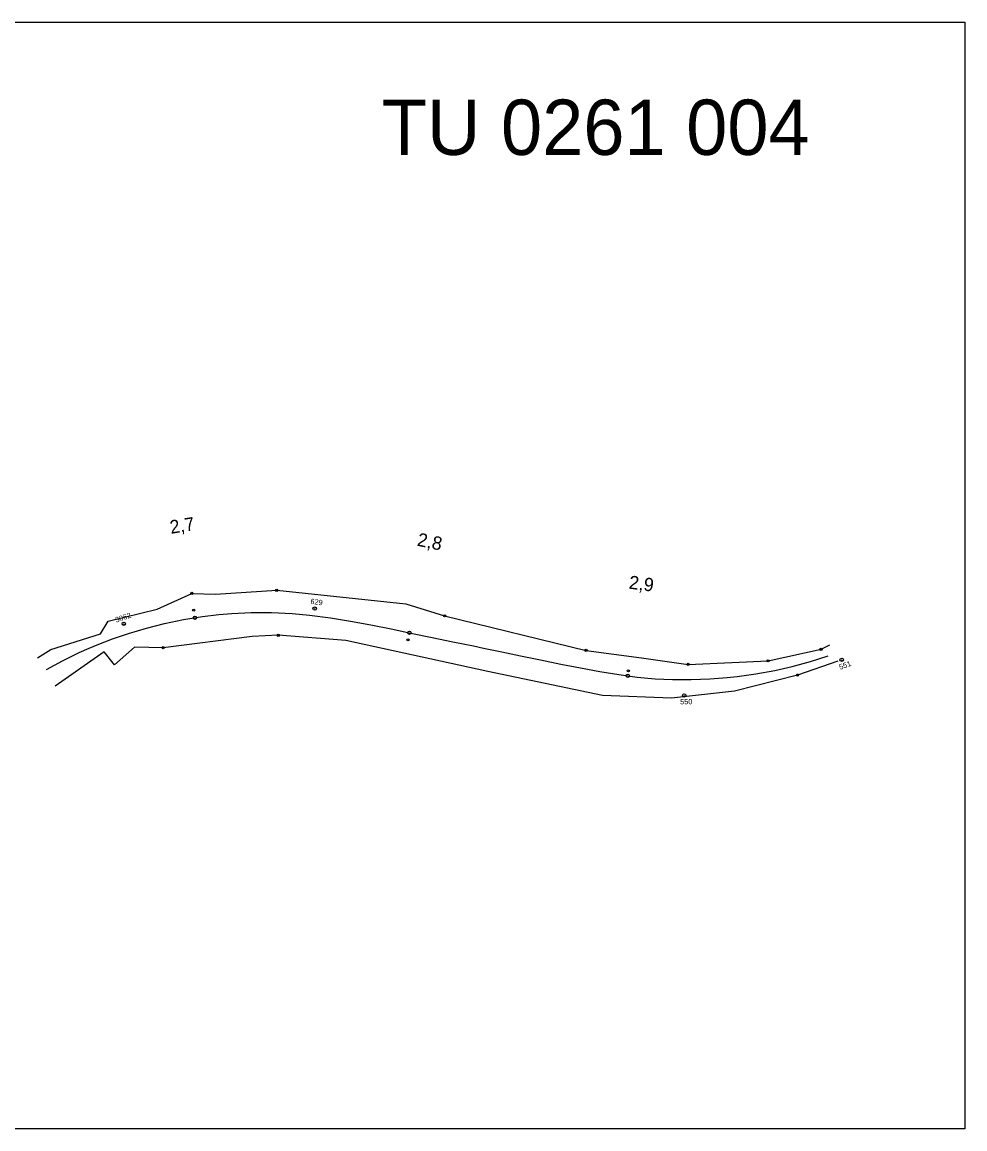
# Model space of a CAD drawing. Extents: x -849500 to -843400, y -1061500 to -1052696.
# Drawn here: x -843826 to -843400, y -1061500 to -1061000 of the extents above; entities that cross this region are included whole.
import ezdxf

# ---------------------------------------------------------------- set-up
doc = ezdxf.new("R2010")
doc.units = 0
for name, color, linetype in [('Level 1', 7, 'Continuous'), ('Level 2', 7, 'Continuous'), ('Vrstva 1', 7, 'Continuous'), ('Vrstva 53', 7, 'Continuous'), ('Vrstva 63', 7, 'Continuous'), ('Vrstva 7', 7, 'Continuous')]:
    doc.layers.add(name, color=color, linetype=linetype)

msp = doc.modelspace()

# ---------------------------------------------------------------- linework, layer by layer
at = {"layer": 'Level 1'}
msp.add_lwpolyline([(-844100, -1061500), (-844100, -1061000), (-843400, -1061000), (-843400, -1061500), (-844100, -1061500)], dxfattribs=at)
at = {"layer": 'Vrstva 1'}
msp.add_lwpolyline([(-843814.8, -1061292.46), (-843807.55, -1061288.51), (-843800.05, -1061284.84), (-843795.59, -1061282.83), (-843792.03, -1061281.34), (-843784.97, -1061278.61), (-843777.74, -1061276.13), (-843769.61, -1061273.72), (-843761.54, -1061271.7), (-843752.93, -1061269.93), (-843744.31, -1061268.56), (-843737, -1061267.68), (-843731.14, -1061267.17), (-843722.35, -1061266.75), (-843713.28, -1061266.75), (-843703.86, -1061267.17), (-843695.99, -1061267.88), (-843686.54, -1061269.1), (-843677.48, -1061270.59), (-843668.34, -1061272.3), (-843659.18, -1061274.15), (-843650.24, -1061275.99), (-843640.69, -1061277.96), (-843631.28, -1061279.9), (-843622.03, -1061281.82), (-843617.49, -1061282.77), (-843609.21, -1061284.48), (-843600.78, -1061286.23), (-843591.65, -1061288.12), (-843582.54, -1061289.99), (-843573.66, -1061291.77), (-843564.83, -1061293.4), (-843556.32, -1061294.8), (-843547.97, -1061295.88), (-843539.88, -1061296.61), (-843532.11, -1061296.98), (-843523.63, -1061297.04), (-843515.26, -1061296.73), (-843507.43, -1061296.12), (-843502.84, -1061295.63), (-843494.35, -1061294.43), (-843485.91, -1061292.87), (-843478.02, -1061291.08), (-843469.68, -1061288.8), (-843461.7, -1061286.27)], dxfattribs=at)
at = {"layer": 'Vrstva 53'}
for p, q in [((-843749.26, -1061258.08), (-843749.16, -1061258.08)), ((-843710.92, -1061256.67), (-843710.82, -1061256.67)), ((-843635.07, -1061268.21), (-843634.97, -1061268.21)), ((-843710.21, -1061277.01), (-843710.11, -1061277.01)), ((-843762.2, -1061282.64), (-843762.1, -1061282.64)), ((-843571.18, -1061283.83), (-843571.08, -1061283.83)), ((-843465, -1061283.35), (-843464.9, -1061283.35)), ((-843488.96, -1061288.55), (-843488.86, -1061288.55)), ((-843525.03, -1061290.18), (-843524.93, -1061290.18)), ((-843475.67, -1061295), (-843475.57, -1061295))]:
    msp.add_line(p, q, dxfattribs=at)
for points in [[(-843818.86, -1061287.16), (-843812.93, -1061283.41), (-843790.42, -1061276.31), (-843787, -1061270.65), (-843764.85, -1061265.22), (-843749.21, -1061258.08), (-843738.44, -1061258.37), (-843710.87, -1061256.67), (-843652.6, -1061262.75), (-843635.02, -1061268.21), (-843571.13, -1061283.83), (-843546.06, -1061287.23), (-843524.98, -1061290.18), (-843505.26, -1061289.35), (-843488.91, -1061288.55), (-843464.95, -1061283.35), (-843461.05, -1061281.3)], [(-843457.33, -1061288.75), (-843475.62, -1061295), (-843504.06, -1061302.23), (-843532.5, -1061305.38), (-843563.75, -1061304.23), (-843615.53, -1061293.42), (-843679.63, -1061279.35), (-843710.16, -1061277.01), (-843722.02, -1061277.52), (-843762.15, -1061282.64), (-843775.05, -1061282.39), (-843784.12, -1061290.32), (-843788.83, -1061284.48), (-843811.01, -1061300.02)]]:
    msp.add_lwpolyline(points, dxfattribs=at)
for centre in [(-843749.21, -1061258.08), (-843710.87, -1061256.67), (-843635.02, -1061268.21), (-843710.16, -1061277.01), (-843762.15, -1061282.64), (-843571.13, -1061283.83), (-843464.95, -1061283.35), (-843524.98, -1061290.18), (-843488.91, -1061288.55), (-843475.62, -1061295)]:
    msp.add_circle(centre, 0.499, dxfattribs=at)
at = {"layer": 'Vrstva 63'}
for p, q in [((-843693.76, -1061264.93), (-843693.66, -1061264.93)), ((-843780.01, -1061271.79), (-843779.91, -1061271.79)), ((-843455.7, -1061288.04), (-843455.6, -1061288.04)), ((-843526.79, -1061304.16), (-843526.69, -1061304.16))]:
    msp.add_line(p, q, dxfattribs=at)
for centre in [(-843693.71, -1061264.93), (-843779.96, -1061271.79), (-843455.65, -1061288.04), (-843526.74, -1061304.16)]:
    msp.add_circle(centre, 0.756, dxfattribs=at)
at = {"layer": 'Vrstva 7'}
for p, q in [((-843748.39, -1061265.69), (-843748.29, -1061265.68)), ((-843651.51, -1061279.09), (-843651.61, -1061279.07)), ((-843551.97, -1061293.07), (-843552.07, -1061293.05))]:
    msp.add_line(p, q, dxfattribs=at)
for centre, radius in [((-843748.34, -1061265.68), 0.5), ((-843747.8, -1061269.11), 0.75), ((-843651.56, -1061279.08), 0.5), ((-843650.9, -1061275.86), 0.75), ((-843552.31, -1061295.32), 0.75), ((-843552.02, -1061293.06), 0.5)]:
    msp.add_circle(centre, radius, dxfattribs=at)

# ---------------------------------------------------------------- texts
at = {"layer": 'Level 2'}
msp.add_text('TU 0261 004', height=25, dxfattribs=at).set_placement((-843663.4, -1061060))
at = {"layer": 'Vrstva 63'}
for s, rotation, p in [('629', 352.6222, (-843695.73, -1061262.79)), ('3062', 18.9301, (-843783.36, -1061271.31)), ('551', 19.9471, (-843456.33, -1061292.62))]:
    msp.add_text(s, height=2.4, rotation=rotation, dxfattribs=at).set_placement(p)
msp.add_text('550', height=2.4, dxfattribs=at).set_placement((-843528.62, -1061308.19))
at = {"layer": 'Vrstva 7'}
for s, rotation, p in [('2,7', 9.0306, (-843758.64, -1061231.19)), ('2,8', 348.3694, (-843647.74, -1061236.49)), ('2,9', 352.6108, (-843552.01, -1061255.91))]:
    msp.add_text(s, height=6, rotation=rotation, dxfattribs=at).set_placement(p)

doc.saveas('drawing.dxf')
